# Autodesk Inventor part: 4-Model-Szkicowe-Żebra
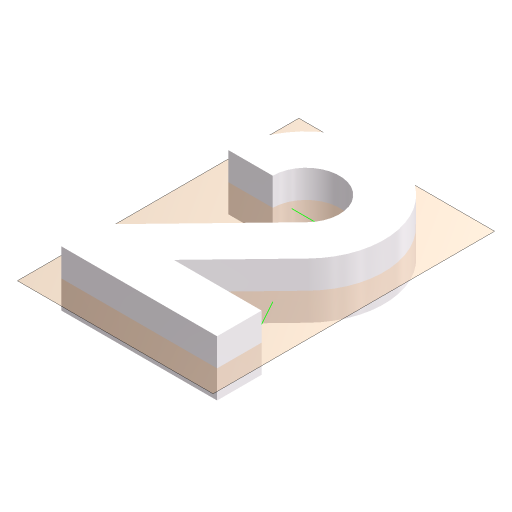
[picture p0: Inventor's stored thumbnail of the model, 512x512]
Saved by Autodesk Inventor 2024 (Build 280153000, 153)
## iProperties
Company: ATC
Shininess: 21.0
Length Units: 11269
Angle Units: 11279
Time Units: 11290
Mass Units: 11283
Length Display Precision: 3
Angle Display Precision: 2
Compacted: True
Created: 2023-03
Part Number: 4-Model-Szkicowe-Żebra
Document SubType Name: Modeling
Designer: Andrzej Jaskulski
Material: Kurs-AJ
Density: 1 g/cm^3
Appearance: Kurs-AJ
Checked By: A.J.
Engr Approved By: Andrzej Jaskulski
Mfg Approved By: Andrzej Jaskulski
Authority: A.J.
Density: 0.0
Volumn: 0.0
Area: 0.0
PropertySet Name: Model Information
Control State: 0
Master: False
Checked Out: False
Title: A.J.: Kurs R2024-MEP
Author: Andrzej Jaskulski
Revision Number: 1/24
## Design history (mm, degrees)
sketch "Zarys dwójki"
  geometry: L1 (140, 0.063)-(0, 0.063) reference; L2 (0, 0.063)-(0, 34.389) reference; L3 (0, 150.063)-(40, 150.063); L4 (140, 0.063)-(140, 40.063); L5 (140, 40.063)-(61.086, 40.063); L6 (61.086, 40.063)-(120.354, 101.437); L7 (91.58, 129.223)-(0, 34.389); A1 r 30 centre (70, 150.063) between (91.58, 129.223) and (40, 150.063); A2 r 70 centre (70, 150.063) between (120.354, 101.437) and (0, 150.063)
  constraints: 14 end point, 4 perpendicular, 4 point on circle, 2 centre point, 2 parallel, 2 tangent, 1 coincident
  dimensions: "d0" = 140 distance of L1.start L1.end; "d1" = 150 vertical distance of A1.centre L1.end; "d2" = 70 horizontal distance of L1.end A1.centre; "d3" = 46 deg angle of L6 L5; "d4" = 150 distance of L3.start L1.end (= d1); "d5" = 30 radius of A1; "d6" = 70 radius of A2
extrude "Extrusion2" new body sketch "Zarys dwójki" stored distance "d12" = 50; taper "d13" = 0 deg
node "Płaszczyzna symetrii"
sketch "Żebro"
  geometry: L1 (-27, 77)-(-11, 48)
  constraints: 2 end point
sketch "Półka"
  geometry: L1 (-91, 158)-(-51, 158)
  constraints: 2 end point
node "Bryła1"
node "Korpusy bryłowe"
node "Korpusy powierzchniowe"
other parameters: "d9" = 90 deg
